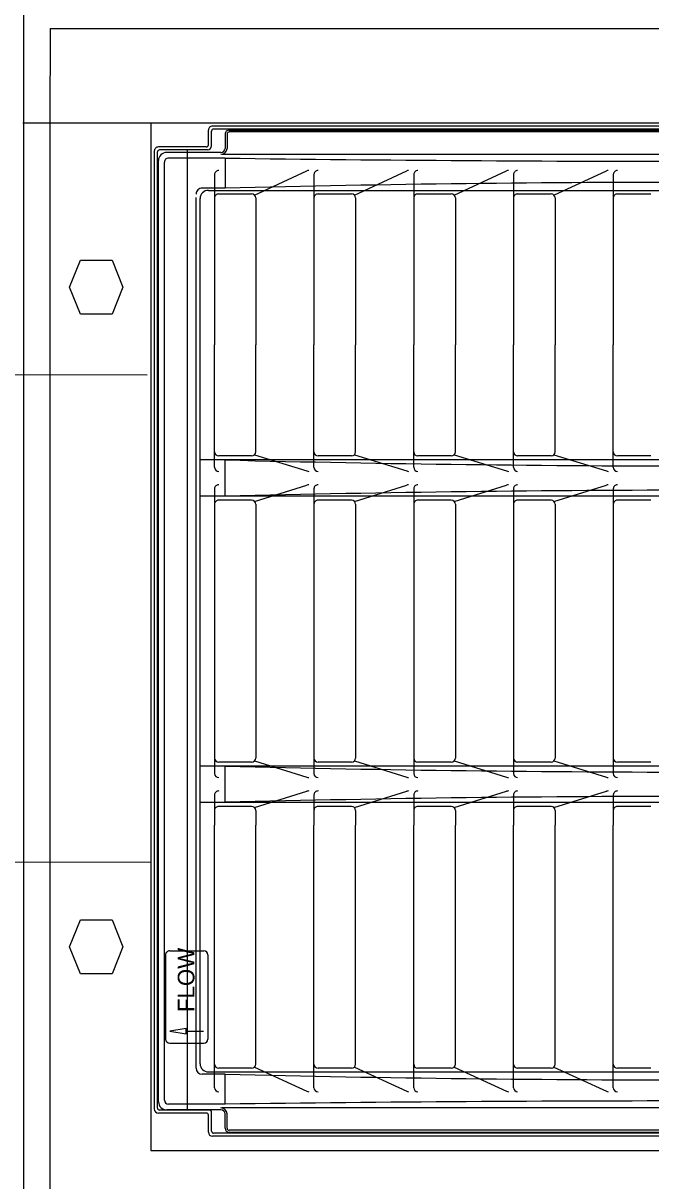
# Model space of a CAD drawing. Extents: x 9.6 to 16.8, y 2.2 to 12.2.
# Drawn here: x 11.244 to 11.815, y 10.461 to 11.515 of the extents above; entities that cross this region are included whole.
import ezdxf

# ---------------------------------------------------------------- set-up
doc = ezdxf.new("R2010")
doc.units = 0
doc.layers.add('DETL-LINE', color=7, linetype='Continuous')
doc.layers.add('DETL-NOTE', color=7, linetype='Continuous')

msp = doc.modelspace()

# ---------------------------------------------------------------- linework, layer by layer
at = {"layer": 'DETL-LINE'}
for p, q in [((11.2446, 11.6582), (11.2446, 10.3172)), ((11.2688, 11.5097), (11.2685, 11.4237)), ((11.2688, 11.5097), (13.517, 11.5097)), ((11.244, 11.4238), (13.5464, 11.4238)), ((11.2685, 11.4237), (11.2685, 10.3938)), ((11.3603, 11.4235), (11.3603, 10.4884)), ((11.4127, 11.4037), (11.4127, 11.4172)), ((11.4156, 11.4028), (11.4156, 11.4163)), ((12.3168, 11.4208), (11.4165, 11.4208)), ((12.3158, 11.4181), (11.4175, 11.4181)), ((11.4297, 11.4135), (11.4297, 11.4005)), ((12.3016, 11.4155), (11.4317, 11.4155)), ((11.3636, 10.5261), (11.3636, 11.3982)), ((11.3664, 10.527), (11.3664, 11.3973)), ((11.4108, 11.4019), (11.3673, 11.4019)), ((11.4118, 11.3991), (11.3683, 11.3991)), ((11.4279, 11.3917), (11.3765, 11.3917)), ((11.3938, 11.3968), (11.3938, 11.3991)), ((11.3938, 10.5253), (11.3938, 11.3968)), ((12.3092, 11.3951), (11.4248, 11.3951)), ((11.4279, 11.3917), (11.4279, 11.3644)), ((11.3727, 10.5342), (11.3727, 11.388)), ((11.4279, 11.3644), (11.4072, 11.3644)), ((11.4127, 11.3623), (12.3206, 11.3623)), ((11.4015, 10.5633), (11.4015, 11.3559)), ((11.4052, 10.5672), (11.4052, 11.355)), ((11.2865, 11.2743), (11.2964, 11.2989)), ((11.2964, 11.2989), (11.3251, 11.2989)), ((11.3251, 11.2989), (11.335, 11.2743)), ((11.2964, 11.2496), (11.2865, 11.2743)), ((11.335, 11.2743), (11.3251, 11.2496)), ((11.3251, 11.2496), (11.2964, 11.2496)), ((11.3569, 11.1942), (10.9589, 11.1952)), ((12.3281, 11.117), (11.4052, 11.117)), ((11.4279, 11.0839), (11.4279, 11.117)), ((12.3281, 11.0839), (11.4052, 11.0839)), ((12.3281, 10.8383), (11.4052, 10.8383)), ((11.4279, 10.8052), (11.4279, 10.8383)), ((12.3281, 10.8052), (11.4052, 10.8052)), ((11.361, 10.7504), (11.0276, 10.7513)), ((11.2865, 10.6738), (11.2964, 10.6984)), ((11.2964, 10.6984), (11.3251, 10.6984)), ((11.3251, 10.6984), (11.3349, 10.6738)), ((11.2964, 10.6492), (11.2865, 10.6738)), ((11.3349, 10.6738), (11.3251, 10.6492)), ((11.3251, 10.6492), (11.2964, 10.6492)), ((11.4127, 10.5599), (12.3206, 10.5599)), ((11.4279, 10.5578), (11.4072, 10.5578)), ((11.4279, 10.5305), (11.4279, 10.5578)), ((11.4279, 10.5305), (11.3765, 10.5305)), ((11.4108, 10.5224), (11.3673, 10.5224)), ((11.4137, 10.5252), (11.3683, 10.5252)), ((11.3938, 10.5252), (11.3938, 10.5253)), ((11.4127, 10.505), (11.4127, 10.5206)), ((11.4156, 10.5059), (11.4156, 10.5233)), ((12.3092, 10.5271), (11.4248, 10.5271)), ((11.4297, 10.5086), (11.4297, 10.5217)), ((12.3016, 10.5067), (11.4317, 10.5067)), ((12.3168, 10.5013), (11.4165, 10.5013)), ((12.3158, 10.5041), (11.4175, 10.5041)), ((11.3604, 10.4884), (13.4162, 10.4884))]:
    msp.add_line(p, q, dxfattribs=at)
for centre, major_axis, start_param, end_param in [((11.4165, 11.4172), (0.00378, 0), 1.570796, 3.141593), ((11.4175, 11.4163), (0.00189, 0), 1.570796, 3.141593), ((11.4317, 11.4135), (0.002, 0), 1.570796, 3.141593), ((11.4108, 11.4037), (0.00189, 0), 4.712389, 6.283185), ((11.4108, 11.4037), (0.00189, 0), 4.712389, 6.283185), ((11.4118, 11.4028), (0.00378, 0), 4.712389, 6.283185), ((11.3673, 11.3982), (0.00378, 0), 1.570796, 3.141593), ((11.3683, 11.3973), (0.00189, 0), 1.570796, 3.141593), ((11.3765, 11.388), (0.00378, 0), 1.570796, 3.141593), ((11.4241, 11.4005), (0.00556, 0), 4.712389, 6.283185), ((11.8667, 42.077), (31.8132, 0), 4.698596, 4.726182), ((11.8667, -5.7521), (17.7494, 0), 1.546073, 1.59552), ((11.4072, 11.3589), (0.00567, 0), 1.570796, 3.141593), ((11.4127, 11.355), (0.00757, 0), 1.570796, 3.141593), ((11.8667, 27.4805), (16.9691, 0), 4.686528, 4.73825), ((11.8667, -5.2797), (16.9691, 0), 1.544936, 1.596657), ((11.8667, 27.2018), (16.9691, 0), 4.686528, 4.73825), ((11.8667, -5.5583), (16.9691, 0), 1.544936, 1.596657), ((11.4072, 10.5633), (0.00567, 0), 3.141593, 4.712389), ((11.4127, 10.5672), (0.00757, 0), 3.141593, 4.712389), ((11.8667, 27.6743), (17.7494, 0), 4.687666, 4.737112), ((11.3765, 10.5342), (0.00378, 0), 3.141593, 4.712389), ((11.8667, -20.1548), (31.8132, 0), 1.557003, 1.584589), ((11.3673, 10.5261), (0.00378, 0), 3.141593, 4.712389), ((11.3683, 10.527), (0.00189, 0), 3.141593, 4.712389), ((11.4108, 10.5206), (0.00189, 0), 0, 1.570796), ((11.4137, 10.5233), (0.00189, 0), 0, 1.570796), ((11.4241, 10.5217), (0.00556, 0), 0, 1.570796), ((11.4317, 10.5086), (0.002, 0), 3.141593, 4.712389), ((11.4165, 10.505), (0.00378, 0), 3.141593, 4.712389), ((11.4175, 10.5059), (0.00189, 0), 3.141593, 4.712389)]:
    msp.add_ellipse(centre, major_axis=major_axis, ratio=0.964639, start_param=start_param, end_param=end_param, dxfattribs=at)
at = {"layer": 'DETL-NOTE'}
for p, q in [((11.4279, 11.4135), (11.4279, 11.4005)), ((11.4317, 11.4172), (12.3016, 11.4172)), ((11.4279, 11.4041), (11.4279, 11.4006)), ((11.4241, 11.3968), (11.3749, 11.3968)), ((11.3673, 10.5326), (11.3673, 11.3895)), ((11.4184, 11.3767), (11.4184, 11.2217)), ((11.4547, 11.3579), (11.5024, 11.38)), ((11.5087, 11.3767), (11.5087, 11.2217)), ((11.5455, 11.3579), (11.5932, 11.38)), ((11.5995, 11.3767), (11.5995, 11.2217)), ((11.6363, 11.3579), (11.684, 11.38)), ((11.6903, 11.3767), (11.6903, 11.2217)), ((11.727, 11.3579), (11.7747, 11.38)), ((11.781, 11.3767), (11.781, 11.2217)), ((11.452, 11.359), (11.4221, 11.359)), ((11.4558, 11.3554), (11.4558, 11.2217)), ((11.5428, 11.359), (11.5125, 11.359)), ((11.5466, 11.3554), (11.5466, 11.2217)), ((11.6336, 11.359), (11.6033, 11.359)), ((11.6374, 11.3554), (11.6374, 11.2217)), ((11.7244, 11.359), (11.694, 11.359)), ((11.7282, 11.3554), (11.7282, 11.2217)), ((11.8152, 11.359), (11.7848, 11.359)), ((11.4184, 11.1102), (11.4184, 11.2217)), ((11.4558, 11.1243), (11.4558, 11.2217)), ((11.5087, 11.1102), (11.5087, 11.2217)), ((11.5466, 11.1243), (11.5466, 11.2217)), ((11.5995, 11.1102), (11.5995, 11.2217)), ((11.6374, 11.1243), (11.6374, 11.2217)), ((11.6903, 11.1102), (11.6903, 11.2217)), ((11.7282, 11.1243), (11.7282, 11.2217)), ((11.781, 11.1102), (11.781, 11.2217)), ((11.452, 11.1206), (11.4221, 11.1206)), ((11.4547, 11.1217), (11.5024, 11.1069)), ((11.5428, 11.1206), (11.5125, 11.1206)), ((11.5455, 11.1217), (11.5932, 11.1069)), ((11.6336, 11.1206), (11.6033, 11.1206)), ((11.6363, 11.1217), (11.684, 11.1069)), ((11.7244, 11.1206), (11.694, 11.1206)), ((11.727, 11.1217), (11.7747, 11.1069)), ((11.8152, 11.1206), (11.7848, 11.1206)), ((11.4184, 11.0907), (11.4184, 10.8315)), ((11.4547, 11.0792), (11.5024, 11.0939)), ((11.5087, 11.0907), (11.5087, 10.8315)), ((11.5455, 11.0792), (11.5932, 11.0939)), ((11.5995, 11.0907), (11.5995, 10.8315)), ((11.6363, 11.0792), (11.684, 11.0939)), ((11.6903, 11.0907), (11.6903, 10.8315)), ((11.727, 11.0792), (11.7747, 11.0939)), ((11.781, 11.0907), (11.781, 10.8315)), ((11.452, 11.0802), (11.4221, 11.0802)), ((11.4558, 11.0766), (11.4558, 10.8456)), ((11.5428, 11.0802), (11.5125, 11.0802)), ((11.5466, 11.0766), (11.5466, 10.8456)), ((11.6336, 11.0802), (11.6033, 11.0802)), ((11.6374, 11.0766), (11.6374, 10.8456)), ((11.7244, 11.0802), (11.694, 11.0802)), ((11.7282, 11.0766), (11.7282, 10.8456)), ((11.8152, 11.0802), (11.7848, 11.0802)), ((11.452, 10.8419), (11.4221, 10.8419)), ((11.4547, 10.843), (11.5024, 10.8282)), ((11.5428, 10.8419), (11.5125, 10.8419)), ((11.5455, 10.843), (11.5932, 10.8282)), ((11.6336, 10.8419), (11.6033, 10.8419)), ((11.6363, 10.843), (11.684, 10.8282)), ((11.7244, 10.8419), (11.694, 10.8419)), ((11.727, 10.843), (11.7747, 10.8282)), ((11.8152, 10.8419), (11.7848, 10.8419)), ((11.4547, 10.8005), (11.5024, 10.8153)), ((11.5455, 10.8005), (11.5932, 10.8153)), ((11.6363, 10.8005), (11.684, 10.8153)), ((11.727, 10.8005), (11.7747, 10.8153)), ((11.4184, 10.812), (11.4184, 10.7844)), ((11.452, 10.8016), (11.4221, 10.8016)), ((11.5087, 10.812), (11.5087, 10.7844)), ((11.5428, 10.8016), (11.5125, 10.8016)), ((11.5995, 10.812), (11.5995, 10.7844)), ((11.6336, 10.8016), (11.6033, 10.8016)), ((11.6903, 10.812), (11.6903, 10.7844)), ((11.7244, 10.8016), (11.694, 10.8016)), ((11.781, 10.812), (11.781, 10.7844)), ((11.8152, 10.8016), (11.7848, 10.8016)), ((11.4558, 10.7979), (11.4558, 10.7844)), ((11.5466, 10.7979), (11.5466, 10.7844)), ((11.6374, 10.7979), (11.6374, 10.7844)), ((11.7282, 10.7979), (11.7282, 10.7844)), ((11.4184, 10.5455), (11.4184, 10.7844)), ((11.4558, 10.5668), (11.4558, 10.7844)), ((11.5087, 10.5455), (11.5087, 10.7844)), ((11.5466, 10.5668), (11.5466, 10.7844)), ((11.5995, 10.5455), (11.5995, 10.7844)), ((11.6374, 10.5668), (11.6374, 10.7844)), ((11.6903, 10.5455), (11.6903, 10.7844)), ((11.7282, 10.5668), (11.7282, 10.7844)), ((11.781, 10.5455), (11.781, 10.7844)), ((11.3737, 10.6664), (11.3737, 10.5897)), ((11.3775, 10.67), (11.4085, 10.67)), ((11.4123, 10.6664), (11.4123, 10.5897)), ((11.3926, 10.597), (11.4083, 10.597)), ((11.3775, 10.586), (11.4085, 10.586)), ((11.452, 10.5632), (11.4221, 10.5632)), ((11.4547, 10.5642), (11.5024, 10.5422)), ((11.5428, 10.5632), (11.5125, 10.5632)), ((11.5455, 10.5642), (11.5932, 10.5422)), ((11.6336, 10.5632), (11.6033, 10.5632)), ((11.6363, 10.5642), (11.684, 10.5422)), ((11.7244, 10.5632), (11.694, 10.5632)), ((11.727, 10.5642), (11.7747, 10.5422)), ((11.8152, 10.5632), (11.7848, 10.5632)), ((11.4241, 10.5253), (11.3749, 10.5253)), ((11.4279, 10.5086), (11.4279, 10.5217)), ((11.4279, 10.518), (11.4279, 10.5216)), ((11.4317, 10.505), (12.3016, 10.505))]:
    msp.add_line(p, q, dxfattribs=at)
msp.add_lwpolyline([(11.3926, 10.5945), (11.3926, 10.5994), (11.3775, 10.597)], close=True, dxfattribs=at)
for centre, major_axis, start_param, end_param in [((11.4317, 11.4135), (0.00378, 0), 1.570796, 3.141593), ((11.3749, 11.3895), (0.00757, 0), 1.570796, 3.141593), ((11.4241, 11.4005), (0.00378, 0), 4.712389, 6.283185), ((11.4221, 11.3767), (0.00378, 0), 1.570796, 3.141593), ((11.504, 11.3767), (0.00378, 0), 1.570796, 2.018093), ((11.5125, 11.3767), (0.00378, 0), 1.570796, 3.141593), ((11.5948, 11.3767), (0.00378, 0), 1.570796, 2.018093), ((11.6033, 11.3767), (0.00378, 0), 1.570796, 3.141593), ((11.6856, 11.3767), (0.00378, 0), 1.570796, 2.018093), ((11.694, 11.3767), (0.00378, 0), 1.570796, 3.141593), ((11.7764, 11.3767), (0.00378, 0), 1.570796, 2.018093), ((11.7848, 11.3767), (0.00378, 0), 1.570796, 3.141593), ((11.4221, 11.3554), (0.00378, 0), 1.570796, 3.141593), ((11.452, 11.3554), (0.00378, 0), 0, 1.570796), ((11.5125, 11.3554), (0.00378, 0), 1.570796, 3.141593), ((11.5428, 11.3554), (0.00378, 0), 0, 1.570796), ((11.6033, 11.3554), (0.00378, 0), 1.570796, 3.141593), ((11.6336, 11.3554), (0.00378, 0), 0, 1.570796), ((11.694, 11.3554), (0.00378, 0), 1.570796, 3.141593), ((11.7244, 11.3554), (0.00378, 0), 0, 1.570796), ((11.7848, 11.3554), (0.00378, 0), 1.570796, 3.141593), ((11.4221, 11.1243), (0.00378, 0), 3.141593, 4.712389), ((11.452, 11.1243), (0.00378, 0), 4.712389, 6.283185), ((11.5125, 11.1243), (0.00378, 0), 3.141593, 4.712389), ((11.5428, 11.1243), (0.00378, 0), 4.712389, 6.283185), ((11.6033, 11.1243), (0.00378, 0), 3.141593, 4.712389), ((11.6336, 11.1243), (0.00378, 0), 4.712389, 6.283185), ((11.694, 11.1243), (0.00378, 0), 3.141593, 4.712389), ((11.7244, 11.1243), (0.00378, 0), 4.712389, 6.283185), ((11.7848, 11.1243), (0.00378, 0), 3.141593, 4.712389), ((11.4221, 11.1102), (0.00378, 0), 3.141593, 4.712389), ((11.5125, 11.1102), (0.00378, 0), 3.141593, 4.712389), ((11.6033, 11.1102), (0.00378, 0), 3.141593, 4.712389), ((11.694, 11.1102), (0.00378, 0), 3.141593, 4.712389), ((11.7848, 11.1102), (0.00378, 0), 3.141593, 4.712389), ((11.504, 11.1102), (0.00378, 0), 4.265092, 4.712389), ((11.5948, 11.1102), (0.00378, 0), 4.265092, 4.712389), ((11.6856, 11.1102), (0.00378, 0), 4.265092, 4.712389), ((11.7764, 11.1102), (0.00378, 0), 4.265092, 4.712389), ((11.4221, 11.0907), (0.00378, 0), 1.570796, 3.141593), ((11.504, 11.0907), (0.00378, 0), 1.570796, 2.018093), ((11.5125, 11.0907), (0.00378, 0), 1.570796, 3.141593), ((11.5948, 11.0907), (0.00378, 0), 1.570796, 2.018093), ((11.6033, 11.0907), (0.00378, 0), 1.570796, 3.141593), ((11.6856, 11.0907), (0.00378, 0), 1.570796, 2.018093), ((11.694, 11.0907), (0.00378, 0), 1.570796, 3.141593), ((11.7764, 11.0907), (0.00378, 0), 1.570796, 2.018093), ((11.7848, 11.0907), (0.00378, 0), 1.570796, 3.141593), ((11.4221, 11.0766), (0.00378, 0), 1.570796, 3.141593), ((11.452, 11.0766), (0.00378, 0), 0, 1.570796), ((11.5125, 11.0766), (0.00378, 0), 1.570796, 3.141593), ((11.5428, 11.0766), (0.00378, 0), 0, 1.570796), ((11.6033, 11.0766), (0.00378, 0), 1.570796, 3.141593), ((11.6336, 11.0766), (0.00378, 0), 0, 1.570796), ((11.694, 11.0766), (0.00378, 0), 1.570796, 3.141593), ((11.7244, 11.0766), (0.00378, 0), 0, 1.570796), ((11.7848, 11.0766), (0.00378, 0), 1.570796, 3.141593), ((11.4221, 10.8456), (0.00378, 0), 3.141593, 4.712389), ((11.452, 10.8456), (0.00378, 0), 4.712389, 6.283185), ((11.5125, 10.8456), (0.00378, 0), 3.141593, 4.712389), ((11.5428, 10.8456), (0.00378, 0), 4.712389, 6.283185), ((11.6033, 10.8456), (0.00378, 0), 3.141593, 4.712389), ((11.6336, 10.8456), (0.00378, 0), 4.712389, 6.283185), ((11.694, 10.8456), (0.00378, 0), 3.141593, 4.712389), ((11.7244, 10.8456), (0.00378, 0), 4.712389, 6.283185), ((11.7848, 10.8456), (0.00378, 0), 3.141593, 4.712389), ((11.4221, 10.8315), (0.00378, 0), 3.141593, 4.712389), ((11.504, 10.8315), (0.00378, 0), 4.265092, 4.712389), ((11.5125, 10.8315), (0.00378, 0), 3.141593, 4.712389), ((11.5948, 10.8315), (0.00378, 0), 4.265092, 4.712389), ((11.6033, 10.8315), (0.00378, 0), 3.141593, 4.712389), ((11.6856, 10.8315), (0.00378, 0), 4.265092, 4.712389), ((11.694, 10.8315), (0.00378, 0), 3.141593, 4.712389), ((11.7764, 10.8315), (0.00378, 0), 4.265092, 4.712389), ((11.7848, 10.8315), (0.00378, 0), 3.141593, 4.712389), ((11.4221, 10.812), (0.00378, 0), 1.570796, 3.141593), ((11.504, 10.812), (0.00378, 0), 1.570796, 2.018093), ((11.5125, 10.812), (0.00378, 0), 1.570796, 3.141593), ((11.5948, 10.812), (0.00378, 0), 1.570796, 2.018093), ((11.6033, 10.812), (0.00378, 0), 1.570796, 3.141593), ((11.6856, 10.812), (0.00378, 0), 1.570796, 2.018093), ((11.694, 10.812), (0.00378, 0), 1.570796, 3.141593), ((11.7764, 10.812), (0.00378, 0), 1.570796, 2.018093), ((11.7848, 10.812), (0.00378, 0), 1.570796, 3.141593), ((11.4221, 10.7979), (0.00378, 0), 1.570796, 3.141593), ((11.452, 10.7979), (0.00378, 0), 0, 1.570796), ((11.5125, 10.7979), (0.00378, 0), 1.570796, 3.141593), ((11.5428, 10.7979), (0.00378, 0), 0, 1.570796), ((11.6033, 10.7979), (0.00378, 0), 1.570796, 3.141593), ((11.6336, 10.7979), (0.00378, 0), 0, 1.570796), ((11.694, 10.7979), (0.00378, 0), 1.570796, 3.141593), ((11.7244, 10.7979), (0.00378, 0), 0, 1.570796), ((11.7848, 10.7979), (0.00378, 0), 1.570796, 3.141593), ((11.3775, 10.6664), (0.00378, 0), 1.570796, 3.141593), ((11.4085, 10.6664), (0.00378, 0), 0, 1.570796), ((11.3775, 10.5897), (0.00378, 0), 3.141593, 4.712389), ((11.4085, 10.5897), (0.00378, 0), 4.712389, 6.283185), ((11.4221, 10.5668), (0.00378, 0), 3.141593, 4.712389), ((11.452, 10.5668), (0.00378, 0), 4.712389, 6.283185), ((11.5125, 10.5668), (0.00378, 0), 3.141593, 4.712389), ((11.5428, 10.5668), (0.00378, 0), 4.712389, 6.283185), ((11.6033, 10.5668), (0.00378, 0), 3.141593, 4.712389), ((11.6336, 10.5668), (0.00378, 0), 4.712389, 6.283185), ((11.694, 10.5668), (0.00378, 0), 3.141593, 4.712389), ((11.7244, 10.5668), (0.00378, 0), 4.712389, 6.283185), ((11.7848, 10.5668), (0.00378, 0), 3.141593, 4.712389), ((11.4221, 10.5455), (0.00378, 0), 3.141593, 4.712389), ((11.504, 10.5455), (0.00378, 0), 4.265092, 4.712389), ((11.5125, 10.5455), (0.00378, 0), 3.141593, 4.712389), ((11.5948, 10.5455), (0.00378, 0), 4.265092, 4.712389), ((11.6033, 10.5455), (0.00378, 0), 3.141593, 4.712389), ((11.6856, 10.5455), (0.00378, 0), 4.265092, 4.712389), ((11.694, 10.5455), (0.00378, 0), 3.141593, 4.712389), ((11.7764, 10.5455), (0.00378, 0), 4.265092, 4.712389), ((11.7848, 10.5455), (0.00378, 0), 3.141593, 4.712389), ((11.3749, 10.5326), (0.00757, 0), 3.141593, 4.712389), ((11.4241, 10.5217), (0.00378, 0), 0, 1.570796), ((11.4317, 10.5086), (0.00378, 0), 3.141593, 4.712389)]:
    msp.add_ellipse(centre, major_axis=major_axis, ratio=0.964639, start_param=start_param, end_param=end_param, dxfattribs=at)

# ---------------------------------------------------------------- texts
msp.add_text('FLOW', height=0.01513, rotation=90, dxfattribs=at).set_placement((11.4, 10.6144))

doc.saveas('drawing.dxf')
